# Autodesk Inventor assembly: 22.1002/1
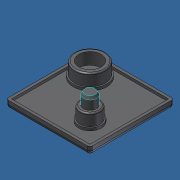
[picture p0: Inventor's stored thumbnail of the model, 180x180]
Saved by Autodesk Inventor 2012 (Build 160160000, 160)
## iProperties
Created: 2012-03
Part Number: 22.1002/1
Document SubType Name: Assembly
Designer: Administrator
Description: END CAP 32X32 Z GRAY
Vendor: S
Mass: 2.95202 g
Surface Area: 33.826 cm^2
Volume: 2.78493 cm^3
Density: 1.06 g/cm^3
Author: Administrator
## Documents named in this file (3)
- Y:\INVENTOR LIBRARIES\PARTS LIBRARY\END CAPS\22.1002_1 END CAP 32X32 Z GRAY.iam
- Y:\INVENTOR LIBRARIES\PARTS LIBRARY\END CAPS\SUBCOMPONENTS\22.1002_1 END CAP 32X32 GRAY.ipt
- Y:\INVENTOR LIBRARIES\PARTS LIBRARY\END CAPS\SUBCOMPONENTS\END CAP DOWEL GRAY.ipt
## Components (2 placed, 2 different names)
1. 22.1002_1 END CAP 32X32 GRAY:1 — Flush:1, Mate:1
2. END CAP DOWEL GRAY:1 — Flush:1, Mate:1
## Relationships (2: Flush 1, Mate 1)
- Flush:1: 22.1002_1 END CAP 32X32 GRAY:1 ↔ END CAP DOWEL GRAY:1
- Mate:1: 22.1002_1 END CAP 32X32 GRAY:1 ↔ END CAP DOWEL GRAY:1
